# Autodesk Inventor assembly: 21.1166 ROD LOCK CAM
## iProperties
Created: 2007-03
Part Number: 21.1166 ROD LOCK CAM
Document SubType Name: Assembly
Designer: Andy Moles
Translation Standard: STEP AP203
File Name: 1000-U167_ASM
Preprocessor: PRO/ENGINEER BY PARAMETRIC TECHNOLOGY CORPORATION, 2001390
Postprocessor: Build: 344b, Release: 11 SP2 - Date: Fri 08/18/2006
Sent Units: MILLIMETERS
Uncertainty: 0.005452955411917
Author: Andy Moles
